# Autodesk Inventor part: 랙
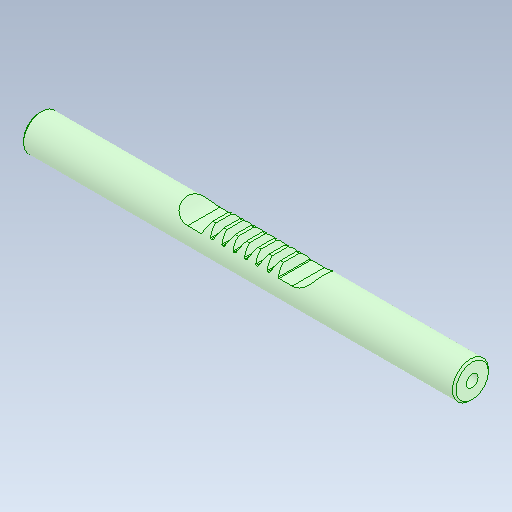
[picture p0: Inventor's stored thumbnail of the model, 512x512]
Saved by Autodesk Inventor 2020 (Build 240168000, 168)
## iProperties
Created: 2024-05
Part Number: 랙
Material: 강철, 탄소
Document SubType Name: Modeling
Designer: oem
Density: 7.85 g/cm^3
Appearance: 기본값
Author: jhkim
Sending System: Autodesk Inventor 2025
Preprocessor: ST-DEVELOPER v20
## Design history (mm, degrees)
feature "솔리드1"
node "솔리드2"
